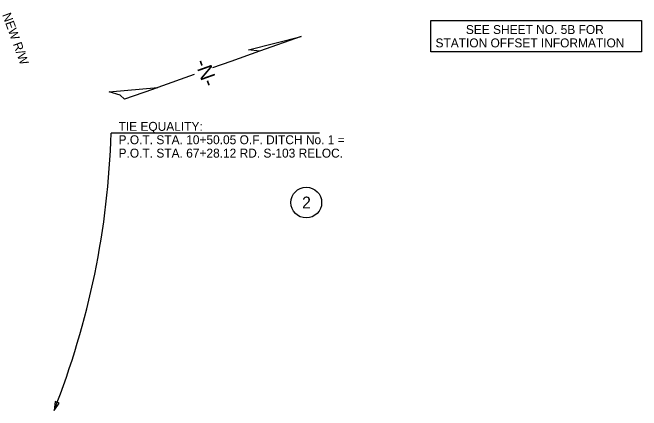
# Model space of a CAD drawing. Extents: x 1964377 to 1966966, y 1116414 to 1123213.
# Drawn here: x 1965593.6 to 1966016.5, y 1122943.5 to 1123211.1 of the extents above; entities that cross this region are included whole.
import ezdxf

# ---------------------------------------------------------------- set-up
doc = ezdxf.new("R2010")
doc.units = 0
for name, color, linetype in [('RD_EX_DV_TX_Prop', 7, 'Continuous'), ('RD_EX_Misc', 7, 'Continuous'), ('RD_HC_Data', 7, 'Continuous'), ('RD_PD_RW_TX', 7, 'Continuous'), ('RD_TX_StaOff', 7, 'Continuous')]:
    doc.layers.add(name, color=color, linetype=linetype)

msp = doc.modelspace()

# ---------------------------------------------------------------- linework, layer by layer
at = {"layer": 'RD_EX_DV_TX_Prop'}
msp.add_circle((1965791.13, 1123083.34), 10.35, dxfattribs=at)
at = {"layer": 'RD_EX_Misc'}
for p, q in [((1965752.26, 1123186.04), (1965787.65, 1123195.13)), ((1965787.65, 1123195.13), (1965759.74, 1123185.17)), ((1965759.74, 1123185.17), (1965740.39, 1123178.27)), ((1965759.74, 1123185.17), (1965752.26, 1123186.04)), ((1965740.39, 1123178.27), (1965728.05, 1123173.87)), ((1965715.73, 1123169.48), (1965691.34, 1123160.78)), ((1965658.67, 1123157.88), (1965691.34, 1123160.78)), ((1965687.64, 1123159.46), (1965668.95, 1123152.79)), ((1965691.34, 1123160.78), (1965687.64, 1123159.46))]:
    msp.add_line(p, q, dxfattribs=at)
msp.add_lwpolyline([(1965668.95, 1123152.79), (1965665.93, 1123155.48), (1965658.67, 1123157.88)], dxfattribs=at)
at = {"layer": 'RD_HC_Data'}
for p, q in [((1965799.96, 1123130.09), (1965659.91, 1123130.09)), ((1965621.5, 1122943.55), (1965621.5, 1122943.55))]:
    msp.add_line(p, q, dxfattribs=at)
msp.add_lwpolyline([(1965622.19, 1122949.51), (1965621.5, 1122943.55), (1965625.07, 1122948.36)], close=True, dxfattribs=at)
msp.add_arc((1965110.25, 1123146.05), 549.89, 338.3911, 358.3364, dxfattribs=at)
at = {"layer": 'RD_TX_StaOff'}
msp.add_lwpolyline([(1965874.97, 1123205.71), (1966016.52, 1123205.71), (1966016.52, 1123184.71), (1965874.97, 1123184.71)], close=True, dxfattribs=at)

# ---------------------------------------------------------------- texts
at = {"layer": 'RD_EX_DV_TX_Prop'}
msp.add_text('2', height=8, dxfattribs=at).set_placement((1965788.3, 1123079.35))
at = {"layer": 'RD_EX_Misc'}
msp.add_text('-N-', height=10, rotation=289.6302, dxfattribs=at).set_placement((1965716.07, 1123177.86))
at = {"layer": 'RD_HC_Data'}
for s, p in [('TIE EQUALITY:', (1965664.91, 1123131.59)), ('P.O.T. STA. 10+50.05 O.F. DITCH No. 1 =', (1965664.91, 1123122.59)), ('P.O.T. STA. 67+28.12 RD. S-103 RELOC.', (1965664.91, 1123113.59))]:
    msp.add_text(s, height=6, dxfattribs=at).set_placement(p)
at = {"layer": 'RD_PD_RW_TX'}
msp.add_text('NEW R/W', height=6, rotation=289.9586, dxfattribs=at).set_placement((1965586.61, 1123209.69))
at = {"layer": 'RD_TX_StaOff'}
for s, p in [('SEE SHEET NO. 5B FOR', (1965898.47, 1123196.71)), ('STATION OFFSET INFORMATION', (1965878.06, 1123187.71))]:
    msp.add_text(s, height=6, dxfattribs=at).set_placement(p)

doc.saveas('drawing.dxf')
